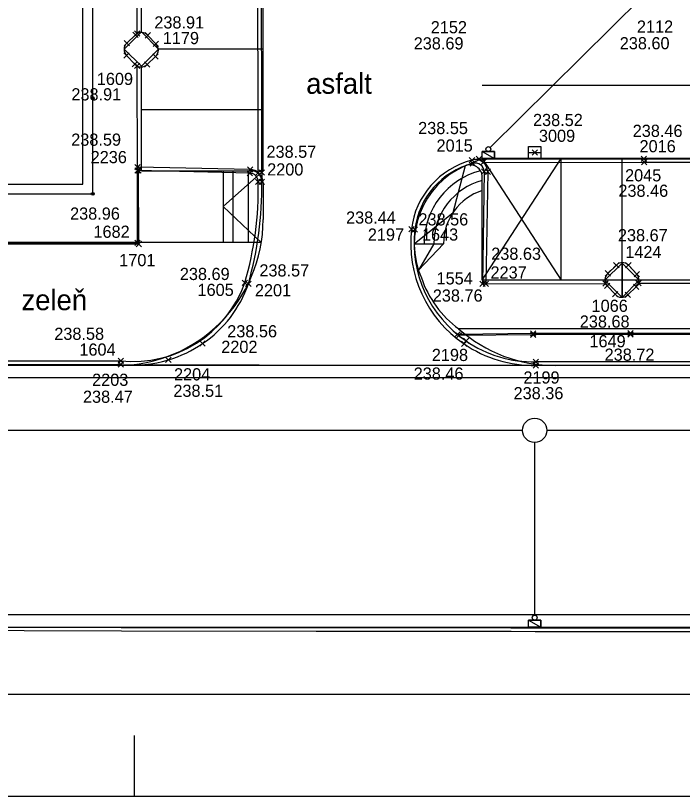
# Model space of a CAD drawing. Extents: x -264165 to -263733, y -1242319 to -1242245.
# Drawn here: x -263975.23 to -263947.85, y -1242319.19 to -1242287.11 of the extents above; entities that cross this region are included whole.
import ezdxf

# ---------------------------------------------------------------- set-up
doc = ezdxf.new("R2010")
doc.units = 0
for name, color, linetype in [('KFA_BOD_CISLO', 7, 'Continuous'), ('KFA_BOD_SYMBOL', 7, 'Continuous'), ('KFA_BOD_VYSKA', 7, 'Continuous'), ('KFA_SO_20-2_OBRUBNIKY_DOLNA_HRANA', 7, 'Continuous'), ('KFA_SO_20-2_OBRUBNIKY_HORNA_HRANA', 7, 'Continuous'), ('KFA_UV_BOD_CISLO', 7, 'Continuous'), ('KFA_UV_BOD_SYMBOL', 7, 'Continuous'), ('KFA_UV_BOD_VYSKA', 7, 'Continuous'), ('POPIS', 7, 'Continuous'), ('PROJEKT_OBRUBNIKY_KOMUNIKACIE', 7, 'Continuous'), ('PROJEKT_TDZ_VODOROVNE', 7, 'Continuous'), ('RAM_NA_TLAC_1-250', 7, 'Continuous'), ('ROZHRANIE_SO_20-1_a_20-2', 7, 'Continuous'), ('SITUACIA_DSP_2D', 7, 'Continuous'), ('SO_20-1_OBRUBNIKY_DOLNA_HRANA', 7, 'Continuous'), ('SO_20-1_OBRUBNIKY_HORNA_HRANA', 7, 'Continuous'), ('ULICNA_VPUST_POKLOP', 7, 'Continuous')]:
    doc.layers.add(name, color=color, linetype=linetype)

msp = doc.modelspace()

# ---------------------------------------------------------------- linework, layer by layer
at = {"layer": 'KFA_BOD_SYMBOL'}
for p, q in [((-263970.425, -1242288.012), (-263970.204, -1242287.791)), ((-263970.204, -1242288.012), (-263970.425, -1242287.791)), ((-263970.35, -1242287.958), (-263970.128, -1242287.737)), ((-263970.128, -1242287.958), (-263970.35, -1242287.737)), ((-263969.917, -1242288.031), (-263969.696, -1242287.809)), ((-263969.696, -1242288.031), (-263969.917, -1242287.809)), ((-263970.781, -1242288.347), (-263970.56, -1242288.127)), ((-263970.56, -1242288.347), (-263970.781, -1242288.127)), ((-263969.583, -1242288.383), (-263969.361, -1242288.163)), ((-263969.361, -1242288.383), (-263969.583, -1242288.163)), ((-263970.785, -1242288.853), (-263970.564, -1242288.632)), ((-263970.564, -1242288.853), (-263970.785, -1242288.632)), ((-263969.593, -1242288.894), (-263969.372, -1242288.674)), ((-263969.372, -1242288.894), (-263969.593, -1242288.674)), ((-263970.446, -1242289.211), (-263970.225, -1242288.991)), ((-263970.225, -1242289.211), (-263970.446, -1242288.991)), ((-263970.348, -1242289.286), (-263970.127, -1242289.066)), ((-263970.127, -1242289.286), (-263970.348, -1242289.066)), ((-263969.937, -1242289.225), (-263969.715, -1242289.004)), ((-263969.715, -1242289.225), (-263969.937, -1242289.004)), ((-263956.601, -1242293.157), (-263956.379, -1242292.936)), ((-263956.379, -1242293.157), (-263956.601, -1242292.936)), ((-263956.312, -1242293.1), (-263956.091, -1242292.879)), ((-263956.091, -1242293.1), (-263956.312, -1242292.879)), ((-263956.145, -1242293.248), (-263955.924, -1242293.026)), ((-263955.924, -1242293.248), (-263956.145, -1242293.026)), ((-263949.539, -1242293.1), (-263949.318, -1242292.879)), ((-263949.318, -1242293.1), (-263949.539, -1242292.879)), ((-263949.533, -1242293.245), (-263949.312, -1242293.025)), ((-263949.312, -1242293.245), (-263949.533, -1242293.025)), ((-263970.34, -1242293.443), (-263970.118, -1242293.221)), ((-263970.118, -1242293.443), (-263970.34, -1242293.221)), ((-263970.34, -1242293.585), (-263970.118, -1242293.363)), ((-263970.118, -1242293.585), (-263970.34, -1242293.363)), ((-263970.296, -1242293.586), (-263970.074, -1242293.365)), ((-263970.074, -1242293.586), (-263970.296, -1242293.365)), ((-263965.709, -1242293.539), (-263965.488, -1242293.319)), ((-263965.488, -1242293.539), (-263965.709, -1242293.319)), ((-263956.565, -1242293.296), (-263956.344, -1242293.076)), ((-263956.344, -1242293.296), (-263956.565, -1242293.076)), ((-263965.726, -1242293.693), (-263965.505, -1242293.471)), ((-263965.505, -1242293.693), (-263965.726, -1242293.471)), ((-263965.383, -1242293.677), (-263965.162, -1242293.455)), ((-263965.162, -1242293.677), (-263965.383, -1242293.455)), ((-263965.237, -1242293.667), (-263965.016, -1242293.445)), ((-263965.016, -1242293.667), (-263965.237, -1242293.445)), ((-263956.104, -1242293.629), (-263955.883, -1242293.407)), ((-263955.883, -1242293.629), (-263956.104, -1242293.407)), ((-263955.954, -1242293.632), (-263955.733, -1242293.41)), ((-263955.733, -1242293.632), (-263955.954, -1242293.41)), ((-263965.382, -1242294.049), (-263965.16, -1242293.828)), ((-263965.16, -1242294.049), (-263965.382, -1242293.828)), ((-263965.235, -1242294.046), (-263965.014, -1242293.825)), ((-263965.014, -1242294.046), (-263965.235, -1242293.825)), ((-263959.089, -1242295.994), (-263958.867, -1242295.772)), ((-263958.867, -1242295.994), (-263959.089, -1242295.772)), ((-263958.946, -1242296.011), (-263958.725, -1242295.789)), ((-263958.725, -1242296.011), (-263958.946, -1242295.789)), ((-263970.332, -1242296.559), (-263970.111, -1242296.339)), ((-263970.111, -1242296.559), (-263970.332, -1242296.339)), ((-263970.285, -1242296.602), (-263970.064, -1242296.38)), ((-263970.064, -1242296.602), (-263970.285, -1242296.38)), ((-263950.671, -1242297.465), (-263950.45, -1242297.245)), ((-263950.45, -1242297.465), (-263950.671, -1242297.245)), ((-263950.179, -1242297.472), (-263949.958, -1242297.252)), ((-263949.958, -1242297.472), (-263950.179, -1242297.252)), ((-263951.018, -1242297.808), (-263950.796, -1242297.586)), ((-263950.796, -1242297.808), (-263951.018, -1242297.586)), ((-263949.834, -1242297.843), (-263949.613, -1242297.623)), ((-263949.613, -1242297.843), (-263949.834, -1242297.623)), ((-263965.927, -1242298.193), (-263965.706, -1242297.971)), ((-263965.706, -1242298.193), (-263965.927, -1242297.971)), ((-263965.785, -1242298.237), (-263965.564, -1242298.015)), ((-263965.564, -1242298.237), (-263965.785, -1242298.015)), ((-263956.17, -1242298.238), (-263955.948, -1242298.018)), ((-263955.948, -1242298.238), (-263956.17, -1242298.018)), ((-263956.03, -1242298.238), (-263955.809, -1242298.018)), ((-263955.809, -1242298.238), (-263956.03, -1242298.018)), ((-263951.111, -1242298.225), (-263950.89, -1242298.005)), ((-263950.89, -1242298.225), (-263951.111, -1242298.005)), ((-263951.052, -1242298.316), (-263950.83, -1242298.096)), ((-263950.83, -1242298.316), (-263951.052, -1242298.096)), ((-263949.854, -1242298.36), (-263949.633, -1242298.139)), ((-263949.633, -1242298.36), (-263949.854, -1242298.139)), ((-263949.758, -1242298.217), (-263949.537, -1242297.995)), ((-263949.537, -1242298.217), (-263949.758, -1242297.995)), ((-263950.717, -1242298.667), (-263950.496, -1242298.445)), ((-263950.496, -1242298.667), (-263950.717, -1242298.445)), ((-263950.204, -1242298.69), (-263949.982, -1242298.468)), ((-263949.982, -1242298.69), (-263950.204, -1242298.468)), ((-263957.201, -1242300.319), (-263956.98, -1242300.097)), ((-263956.98, -1242300.319), (-263957.201, -1242300.097)), ((-263954.089, -1242300.282), (-263953.867, -1242300.062)), ((-263953.867, -1242300.282), (-263954.089, -1242300.062)), ((-263954.089, -1242300.333), (-263953.867, -1242300.112)), ((-263953.867, -1242300.333), (-263954.089, -1242300.112)), ((-263950.095, -1242300.272), (-263949.875, -1242300.052)), ((-263949.875, -1242300.272), (-263950.095, -1242300.052)), ((-263950.095, -1242300.323), (-263949.875, -1242300.102)), ((-263949.875, -1242300.323), (-263950.095, -1242300.102)), ((-263957.139, -1242300.367), (-263956.918, -1242300.147)), ((-263956.918, -1242300.367), (-263957.139, -1242300.147)), ((-263956.842, -1242300.586), (-263956.621, -1242300.366)), ((-263956.621, -1242300.586), (-263956.842, -1242300.366)), ((-263967.663, -1242300.691), (-263967.442, -1242300.47)), ((-263967.442, -1242300.691), (-263967.663, -1242300.47)), ((-263956.926, -1242300.708), (-263956.704, -1242300.487)), ((-263956.704, -1242300.708), (-263956.926, -1242300.487)), ((-263971.024, -1242301.4), (-263970.802, -1242301.18)), ((-263970.802, -1242301.4), (-263971.024, -1242301.18)), ((-263971.023, -1242301.549), (-263970.802, -1242301.328)), ((-263970.802, -1242301.549), (-263971.023, -1242301.328)), ((-263969.071, -1242301.36), (-263968.85, -1242301.14)), ((-263968.85, -1242301.36), (-263969.071, -1242301.14)), ((-263953.973, -1242301.441), (-263953.752, -1242301.22)), ((-263953.752, -1242301.441), (-263953.973, -1242301.22)), ((-263953.973, -1242301.588), (-263953.752, -1242301.367)), ((-263953.752, -1242301.588), (-263953.973, -1242301.367))]:
    msp.add_line(p, q, dxfattribs=at)
at = {"layer": 'KFA_SO_20-2_OBRUBNIKY_DOLNA_HRANA'}
for p, q in [((-263956.202, -1242292.989), (-263956.49, -1242293.046)), ((-263965.599, -1242293.429), (-263970.229, -1242293.332)), ((-263965.127, -1242293.556), (-263965.124, -1242293.935))]:
    msp.add_line(p, q, dxfattribs=at)
for points in [[(-263965.273, -1242293.566), (-263965.279, -1242283.55), (-263965.289, -1242270.846)], [(-263965.127, -1242293.556), (-263965.137, -1242283.552), (-263965.143, -1242270.987)], [(-263956.202, -1242292.989), (-263949.428, -1242292.989), (-263939.423, -1242292.99), (-263929.237, -1242292.989)], [(-263956.035, -1242293.137), (-263949.422, -1242293.135), (-263939.424, -1242293.133), (-263929.555, -1242293.133)], [(-263955.844, -1242293.521), (-263955.92, -1242298.128)]]:
    msp.add_lwpolyline(points, dxfattribs=at)
for centre, major_axis, ratio, start_param, end_param in [((-263955.768, -1242296.156), (-2.482, -2.14), 0.96746, 4.242283, 5.470279), ((-263956.35, -1242293.533), (-0.239, 0.447), 0.999291, 4.244856, 6.070445), ((-263965.612, -1242293.917), (0.451, -0.189), 0.998943, 0.361501, 1.941121), ((-263975.124, -1242294.767), (1.6, 11.839), 0.833992, 4.538826, 4.894527), ((-263953.969, -1242296.438), (-5.036, -0.207), 0.999986, 6.131722, 7.212659), ((-263970.302, -1242296.531), (2.317, 4.313), 0.999794, 4.231365, 4.873428), ((-263970.409, -1242296.372), (3.223, 3.948), 0.997928, 4.115934, 4.423221), ((-263953.959, -1242296.438), (-4.95, -1.004), 0.997814, 0.769968, 1.390257), ((-263970.424, -1242296.405), (5.06, -0.539), 0.993811, 4.721762, 5.109666)]:
    msp.add_ellipse(centre, major_axis=major_axis, ratio=ratio, start_param=start_param, end_param=end_param, dxfattribs=at)
at = {"layer": 'KFA_SO_20-2_OBRUBNIKY_HORNA_HRANA'}
for p, q in [((-263970.239, -1242287.847), (-263970.248, -1242281.638)), ((-263970.671, -1242288.237), (-263970.314, -1242287.901)), ((-263969.807, -1242287.92), (-263969.472, -1242288.273)), ((-263970.335, -1242289.101), (-263970.675, -1242288.742)), ((-263969.482, -1242288.784), (-263969.826, -1242289.114)), ((-263950.907, -1242297.697), (-263950.561, -1242297.355)), ((-263950.068, -1242297.362), (-263949.724, -1242297.733)), ((-263949.648, -1242298.106), (-263943.489, -1242298.079)), ((-263950.606, -1242298.556), (-263950.941, -1242298.206)), ((-263949.743, -1242298.249), (-263950.093, -1242298.579))]:
    msp.add_line(p, q, dxfattribs=at)
for points in [[(-263965.616, -1242293.582), (-263970.229, -1242293.474), (-263970.237, -1242289.176)], [(-264048.312, -1242296.489), (-264028.434, -1242296.487), (-264007.811, -1242296.484), (-263989.348, -1242296.492), (-263970.175, -1242296.491), (-263970.185, -1242293.475)], [(-264048.263, -1242296.44), (-264028.48, -1242296.445), (-264007.857, -1242296.442), (-263989.394, -1242296.45), (-263970.221, -1242296.449), (-263970.229, -1242293.474)], [(-263955.993, -1242293.518), (-263956.059, -1242298.128), (-263951.001, -1242298.115)], [(-263929.02, -1242300.176), (-263931.041, -1242300.176), (-263941.016, -1242300.164), (-263949.985, -1242300.162), (-263953.978, -1242300.172), (-263957.09, -1242300.208)], [(-263929.075, -1242300.226), (-263931.041, -1242300.226), (-263941.016, -1242300.214), (-263949.985, -1242300.212), (-263953.978, -1242300.222), (-263957.029, -1242300.257)]]:
    msp.add_lwpolyline(points, dxfattribs=at)
for centre, major_axis, ratio, start_param, end_param in [((-263970.07, -1242288.159), (-0.355, 0.013), 0.999288, 3.917935, 5.506843), ((-263970.424, -1242288.491), (0.003, 0.355), 0.999593, 0.778416, 2.363176), ((-263969.724, -1242288.524), (0.149, 0.323), 0.999988, 4.324643, 5.928423), ((-263970.074, -1242288.863), (-0.351, -0.041), 0.999905, 0.622142, 2.233058), ((-263955.804, -1242296.126), (-2.333, -2.037), 0.964506, 4.227389, 5.472895), ((-263956.343, -1242293.518), (-0.234, 0.261), 0.998767, 3.98175, 5.871809), ((-263965.619, -1242293.93), (0.033, 0.347), 0.999874, 4.786425, 6.369423), ((-263974.901, -1242294.791), (1.539, 11.392), 0.83473, 4.533478, 4.89912), ((-263954.001, -1242296.449), (-4.851, -0.368), 0.999992, 6.094406, 7.182473), ((-263950.318, -1242297.613), (-0.265, -0.236), 0.99955, 3.200824, 4.73946), ((-263950.679, -1242297.968), (-0.024, -0.353), 0.999608, 3.907407, 5.517371), ((-263949.989, -1242297.982), (0.116, 0.345), 0.998504, 4.209798, 5.789463), ((-263970.392, -1242296.461), (-2.525, -4.15), 0.999251, 0.439488, 1.776776), ((-263950.339, -1242298.332), (0.271, -0.22), 0.999352, 4.522069, 6.177032), ((-263953.988, -1242296.531), (-4.625, -1.315), 0.998389, 0.686812, 1.320267)]:
    msp.add_ellipse(centre, major_axis=major_axis, ratio=ratio, start_param=start_param, end_param=end_param, dxfattribs=at)
at = {"layer": 'KFA_UV_BOD_SYMBOL'}
for p, q in [((-263954.023, -1242292.845), (-263953.802, -1242292.623)), ((-263953.802, -1242292.845), (-263954.023, -1242292.623))]:
    msp.add_line(p, q, dxfattribs=at)
at = {"layer": 'PROJEKT_OBRUBNIKY_KOMUNIKACIE'}
for p, q in [((-263965.068, -1242293.482), (-263965.068, -1242270.982)), ((-263970.068, -1242287.775), (-263970.068, -1242281.649)), ((-263970.068, -1242293.482), (-263970.068, -1242289.189)), ((-263956.769, -1242293.279), (-263956.068, -1242292.982)), ((-263929.58, -1242292.982), (-263956.068, -1242292.982)), ((-263970.068, -1242293.482), (-263965.568, -1242293.482)), ((-263966.714, -1242293.482), (-263966.714, -1242296.432)), ((-263965.068, -1242293.982), (-263965.068, -1242295.482)), ((-263956.068, -1242297.982), (-263956.068, -1242293.737)), ((-263950.324, -1242297.275), (-263951.031, -1242297.982)), ((-263949.617, -1242297.982), (-263950.324, -1242297.275)), ((-263950.324, -1242297.275), (-263950.324, -1242298.689)), ((-263950.324, -1242298.689), (-263950.324, -1242297.275)), ((-263929.58, -1242297.982), (-263956.068, -1242297.982)), ((-263951.031, -1242297.982), (-263950.324, -1242298.689)), ((-263950.324, -1242298.689), (-263949.617, -1242297.982)), ((-263928.612, -1242299.982), (-263957.036, -1242299.982)), ((-263971.068, -1242301.482), (-264112.961, -1242301.482)), ((-263932.58, -1242301.482), (-263953.068, -1242301.482)), ((-263980.94, -1242312.232), (-263924.192, -1242312.232)), ((-264038.443, -1242314.982), (-263836.403, -1242314.982))]:
    msp.add_line(p, q, dxfattribs=at)
for points in [[(-264042.568, -1242294.032), (-263972.468, -1242294.032), (-263972.468, -1242244.935)], [(-263970.068, -1242287.775), (-263969.361, -1242288.482), (-263970.068, -1242289.189), (-263970.775, -1242288.482), (-263970.068, -1242287.775)], [(-263958.859, -1242296.482), (-263957.268, -1242295.199), (-263956.756, -1242293.273)], [(-263965.214, -1242293.629), (-263966.714, -1242294.957), (-263965.143, -1242296.432)], [(-263965.143, -1242296.432), (-264120.018, -1242296.432), (-264120.282, -1242296.432)], [(-263958.859, -1242296.482), (-263957.659, -1242296.482), (-263958.688, -1242297.562)]]:
    msp.add_lwpolyline(points, dxfattribs=at)
for centre, radius, start, end in [((-263955.359, -1242296.482), 3.5, 113.7599, 203.5782), ((-263956.568, -1242293.737), 0.5, 0, 113.7599), ((-263965.568, -1242293.982), 0.5, 0, 90), ((-263955.359, -1242296.482), 2.3, 107.9469, 180), ((-263971.068, -1242295.482), 6, 270, 0), ((-263954.444, -1242296.485), 4.353, 198.7173, 233.4513), ((-263953.068, -1242295.482), 6, 228.5904, 270)]:
    msp.add_arc(centre, radius, start, end, dxfattribs=at)
at = {"layer": 'PROJEKT_TDZ_VODOROVNE'}
for p, q in [((-263965.068, -1242288.482), (-263969.361, -1242288.482)), ((-263929.58, -1242289.982), (-263956.068, -1242289.982)), ((-263965.068, -1242290.982), (-263970.068, -1242290.982)), ((-263956.069, -1242297.982), (-263952.825, -1242292.982)), ((-263956.069, -1242292.982), (-263952.825, -1242297.982)), ((-263952.824, -1242297.982), (-263952.824, -1242292.982)), ((-263950.324, -1242297.275), (-263950.324, -1242292.982)), ((-263953.068, -1242301.482), (-263971.068, -1242301.482)), ((-264112.961, -1242301.982), (-263971.806, -1242301.982)), ((-263971.806, -1242301.982), (-263953.068, -1242301.982)), ((-263953.068, -1242301.982), (-263932.58, -1242301.982)), ((-263842.661, -1242311.732), (-263980.94, -1242311.732))]:
    msp.add_line(p, q, dxfattribs=at)
msp.add_arc((-263955.359, -1242296.482), 3.5, 90, 101.6826, dxfattribs=at)
at = {"layer": 'RAM_NA_TLAC_1-250'}
msp.add_line((-263970.363, -1242316.685), (-263970.363, -1242319.185), dxfattribs=at)
msp.add_lwpolyline([(-264165.363, -1242244.935), (-263732.863, -1242244.935), (-263732.863, -1242319.185), (-264165.363, -1242319.185)], close=True, dxfattribs=at)
at = {"layer": 'ROZHRANIE_SO_20-1_a_20-2'}
msp.add_line((-263970.912, -1242301.438), (-263953.862, -1242301.477), dxfattribs=at)
at = {"layer": 'SITUACIA_DSP_2D'}
for p, q in [((-263972.468, -1242294.032), (-263972.468, -1242244.935)), ((-263972.068, -1242294.432), (-263972.068, -1242255.057)), ((-263970.068, -1242287.775), (-263970.068, -1242281.649)), ((-263955.747, -1242292.522), (-263947.464, -1242284.334)), ((-263970.068, -1242293.482), (-263970.068, -1242289.189)), ((-263972.128, -1242290.495), (-263972.008, -1242290.495)), ((-263972.068, -1242290.555), (-263972.068, -1242290.435)), ((-263956.068, -1242292.692), (-263955.568, -1242292.692)), ((-263956.068, -1242292.982), (-263956.068, -1242292.692)), ((-263956.068, -1242292.692), (-263955.568, -1242292.982)), ((-263956.068, -1242292.692), (-263955.568, -1242292.982)), ((-263955.568, -1242292.692), (-263956.068, -1242292.692)), ((-263955.568, -1242292.692), (-263955.568, -1242292.982)), ((-263955.568, -1242292.982), (-263955.568, -1242292.692)), ((-263955.568, -1242292.982), (-263956.068, -1242292.982)), ((-263970.068, -1242293.482), (-263965.568, -1242293.482)), ((-263966.314, -1242293.482), (-263966.314, -1242296.432)), ((-263965.684, -1242293.482), (-263965.684, -1242296.432)), ((-263965.068, -1242293.982), (-263965.068, -1242295.482)), ((-263956.068, -1242297.982), (-263956.068, -1242293.737)), ((-264042.568, -1242294.032), (-263972.468, -1242294.032)), ((-264045.118, -1242294.432), (-263972.068, -1242294.432)), ((-263972.128, -1242294.432), (-263972.008, -1242294.432)), ((-263972.068, -1242294.492), (-263972.068, -1242294.372)), ((-263929.58, -1242297.982), (-263956.068, -1242297.982)), ((-263928.612, -1242299.982), (-263957.036, -1242299.982)), ((-263971.068, -1242301.482), (-264112.961, -1242301.482)), ((-263932.58, -1242301.482), (-263953.068, -1242301.482)), ((-263954.413, -1242304.147), (-264003.396, -1242304.147)), ((-263904.413, -1242304.147), (-263953.413, -1242304.147)), ((-263953.913, -1242311.742), (-263953.913, -1242304.647)), ((-263954.163, -1242311.942), (-263953.663, -1242311.942)), ((-263954.163, -1242312.232), (-263954.163, -1242311.942)), ((-263954.163, -1242311.942), (-263953.663, -1242312.232)), ((-263954.163, -1242311.942), (-263953.663, -1242312.232)), ((-263953.663, -1242311.942), (-263954.163, -1242311.942)), ((-263953.663, -1242311.942), (-263953.663, -1242312.232)), ((-263953.663, -1242312.232), (-263953.663, -1242311.942)), ((-263980.94, -1242312.232), (-263857.327, -1242312.232)), ((-263953.663, -1242312.232), (-263954.163, -1242312.232)), ((-264038.443, -1242314.982), (-263836.403, -1242314.982))]:
    msp.add_line(p, q, dxfattribs=at)
for points in [[(-263970.068, -1242287.775), (-263969.361, -1242288.482), (-263970.068, -1242289.189), (-263970.775, -1242288.482)], [(-263949.617, -1242297.982), (-263950.324, -1242297.275), (-263951.031, -1242297.982), (-263950.324, -1242298.689)]]:
    msp.add_lwpolyline(points, close=True, dxfattribs=at)
for points in [[(-263965.143, -1242296.432), (-264120.018, -1242296.432), (-264120.282, -1242296.432)], [(-263958.859, -1242296.482), (-263958.059, -1242296.482), (-263958.688, -1242297.562)]]:
    msp.add_lwpolyline(points, dxfattribs=at)
for centre, radius in [((-263972.068, -1242290.495), 0.06), ((-263955.818, -1242292.592), 0.1), ((-263972.068, -1242294.432), 0.06), ((-263953.913, -1242304.147), 0.5), ((-263953.913, -1242311.842), 0.1)]:
    msp.add_circle(centre, radius, dxfattribs=at)
for centre, radius, start, end in [((-263955.359, -1242296.482), 3.5, 113.7599, 203.5782), ((-263956.568, -1242293.737), 0.5, 0, 113.7599), ((-263965.568, -1242293.982), 0.5, 0, 90), ((-263955.359, -1242296.482), 3.1, 104.5457, 180), ((-263955.359, -1242296.482), 2.7, 105.2176, 180), ((-263971.068, -1242295.482), 6, 270, 0), ((-263954.444, -1242296.485), 4.353, 198.7173, 233.4513), ((-263953.068, -1242295.482), 6, 228.5904, 270)]:
    msp.add_arc(centre, radius, start, end, dxfattribs=at)
at = {"layer": 'SO_20-1_OBRUBNIKY_DOLNA_HRANA'}
for points in [[(-263993.952, -1242301.425), (-263986.921, -1242301.437), (-263979.924, -1242301.441), (-263972.919, -1242301.445), (-263970.912, -1242301.438)], [(-263931.888, -1242301.474), (-263942.877, -1242301.476), (-263953.862, -1242301.477)], [(-264033.805, -1242309.499), (-264025.829, -1242309.934), (-264015.848, -1242310.539), (-264003.863, -1242311.243), (-263994.874, -1242311.606), (-263986.882, -1242311.907), (-263978.856, -1242312.215), (-263970.892, -1242312.243), (-263962.891, -1242312.248), (-263954.893, -1242312.255), (-263953.892, -1242312.266), (-263946.9, -1242312.261), (-263936.904, -1242312.253), (-263927.909, -1242312.236)]]:
    msp.add_lwpolyline(points, dxfattribs=at)
at = {"layer": 'SO_20-1_OBRUBNIKY_HORNA_HRANA'}
for points in [[(-263993.949, -1242301.276), (-263986.923, -1242301.287), (-263979.923, -1242301.293), (-263972.92, -1242301.295), (-263970.913, -1242301.29)], [(-263931.888, -1242301.33), (-263942.861, -1242301.337), (-263953.862, -1242301.33)], [(-264033.819, -1242309.643), (-264025.833, -1242310.082), (-264015.854, -1242310.687), (-264003.872, -1242311.39), (-263994.881, -1242311.753), (-263986.886, -1242312.056), (-263978.896, -1242312.359), (-263970.883, -1242312.387), (-263962.888, -1242312.396), (-263954.878, -1242312.403), (-263953.896, -1242312.41), (-263946.895, -1242312.406), (-263936.899, -1242312.396), (-263927.906, -1242312.382)]]:
    msp.add_lwpolyline(points, dxfattribs=at)
at = {"layer": 'ULICNA_VPUST_POKLOP'}
msp.add_line((-263953.912, -1242292.734), (-263953.912, -1242292.734), dxfattribs=at)
msp.add_lwpolyline([(-263954.162, -1242292.734), (-263954.162, -1242292.484), (-263953.662, -1242292.484), (-263953.662, -1242292.984), (-263954.162, -1242292.984), (-263954.162, -1242292.734), (-263953.662, -1242292.734)], dxfattribs=at)

# ---------------------------------------------------------------- texts
at = {"layer": 'KFA_BOD_CISLO'}
for s, p in [('2152', (-263958.183, -1242287.836)), ('2112', (-263949.716, -1242287.809)), ('1179', (-263969.189, -1242288.281)), ('1609', (-263971.898, -1242289.959)), ('2015', (-263957.946, -1242292.696)), ('2016', (-263949.609, -1242292.724)), ('2236', (-263972.151, -1242293.171)), ('2200', (-263964.902, -1242293.677)), ('2045', (-263950.203, -1242293.919)), ('1682', (-263972.036, -1242296.237)), ('2197', (-263960.767, -1242296.354)), ('1643', (-263958.545, -1242296.353)), ('1424', (-263950.194, -1242297.071)), ('1701', (-263970.977, -1242297.403)), ('2237', (-263955.729, -1242297.91)), ('1554', (-263957.945, -1242298.153)), ('1605', (-263967.762, -1242298.626)), ('2201', (-263965.406, -1242298.64)), ('1066', (-263951.578, -1242299.279)), ('1649', (-263951.666, -1242300.736)), ('1604', (-263972.615, -1242301.079)), ('2202', (-263966.787, -1242300.965)), ('2198', (-263958.139, -1242301.299)), ('2204', (-263968.727, -1242302.095)), ('2199', (-263954.378, -1242302.226)), ('2203', (-263972.091, -1242302.319))]:
    msp.add_text(s, height=0.5, dxfattribs=at).set_placement(p)
at = {"layer": 'KFA_BOD_VYSKA'}
for s, p in [('238.91', (-263969.537, -1242287.638)), ('238.69', (-263958.883, -1242288.499)), ('238.60', (-263950.421, -1242288.493)), ('238.91', (-263972.943, -1242290.592)), ('238.55', (-263958.701, -1242291.977)), ('238.46', (-263949.889, -1242292.092)), ('238.59', (-263972.949, -1242292.454)), ('238.57', (-263964.93, -1242292.951)), ('238.46', (-263950.477, -1242294.553)), ('238.96', (-263972.996, -1242295.492)), ('238.44', (-263961.662, -1242295.655)), ('238.56', (-263958.689, -1242295.729)), ('238.67', (-263950.496, -1242296.38)), ('238.63', (-263955.699, -1242297.141)), ('238.69', (-263968.488, -1242297.972)), ('238.57', (-263965.222, -1242297.826)), ('238.76', (-263958.099, -1242298.859)), ('238.68', (-263952.062, -1242299.927)), ('238.58', (-263973.645, -1242300.43)), ('238.56', (-263966.542, -1242300.326)), ('238.72', (-263951.042, -1242301.288)), ('238.46', (-263958.884, -1242302.065)), ('238.51', (-263968.754, -1242302.771)), ('238.36', (-263954.781, -1242302.869)), ('238.47', (-263972.467, -1242303.016))]:
    msp.add_text(s, height=0.5, dxfattribs=at).set_placement(p)
at = {"layer": 'KFA_UV_BOD_CISLO'}
msp.add_text('3009', height=0.5, dxfattribs=at).set_placement((-263953.74, -1242292.296))
at = {"layer": 'KFA_UV_BOD_VYSKA'}
msp.add_text('238.52', height=0.5, dxfattribs=at).set_placement((-263953.983, -1242291.646))
at = {"layer": 'POPIS'}
for s, p in [('asfalt', (-263963.298, -1242290.32)), ('zeleň', (-263974.993, -1242299.211))]:
    msp.add_text(s, height=0.8438, dxfattribs=at).set_placement(p)

doc.saveas('drawing.dxf')
